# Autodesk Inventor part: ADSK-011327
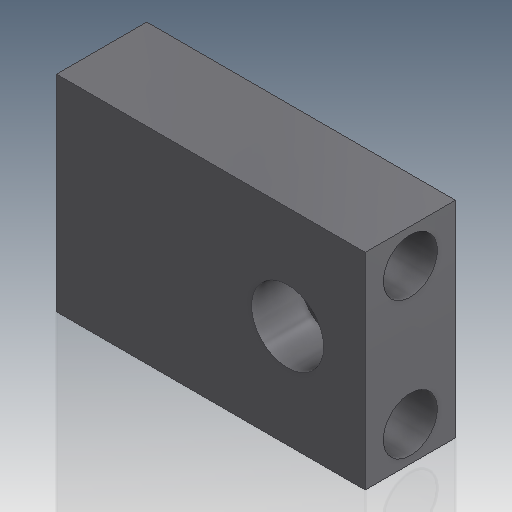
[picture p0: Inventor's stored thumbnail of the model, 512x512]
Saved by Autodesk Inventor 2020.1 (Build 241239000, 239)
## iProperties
Created: 1999-12
Part Number: ADSK-011327
Material: Acier doux
Description: PLT-03,FH,CP,10,022,032,556,BLOCK,MOUNTING
Document SubType Name: Modeling
Designer: sspink
Density: 7.86 g/cm^3
Appearance: Metal-Steel(Polish)
Mass: 782.796 g
Surface Area: 232.844 cm^2
Volume: 99.5924 cm^3
Control State: 0
Checked Out: False
Last Check In By: sspink
Last Check In Date: 1999-12-22
Master: False
Shininess: 0.0
Length Units: 11269
Angle Units: 11279
Time Units: 11290
Mass Units: 11283
Length Display Precision: 3
Angle Display Precision: 2
Compacted: True
Dimensions: 85,5x57x25 mm
Mass: 0,783 kg
DocNumber: ADSK-011327.ipt
Folder: 01 - Themengebiete\Simplification\01 - Packaging machine\
VDS_Category: 3D Komponenten
Density: 0.0
Volumn: 0.0
Area: 0.0
PropertySet Name: Model Information
Author: sspink
Revision Number: -
Title: fixing plate
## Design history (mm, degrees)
sketch "Skizze4"
  geometry: C1 r 6.75 at (-21.25, 0) reference; 2 further points
  constraints: 1 coincident
hole "Bohrung3" sketch "Skizze4" at (-21.25, 0) diameter "d22" = 25; stored, may be unused: countersink angle "d26" = 82 deg, drill point angle "d28" = 0 deg; dims "d23" = 6, "d24" = 20, "d25" = 13.5, "d27" = 6
sketch "Sketch3"
  geometry: L1 (0, 57)-(-25, 57) reference; L2 (-12.5, 47.5)-(-12.5, 9.5); L3 (-25, 57)-(-25, 0) reference; 3 further points
  constraints: 3 midpoint, 2 end point, 1 horizontal alignment, 1 vertical, 1 vertical alignment
  dimensions: "d20" = 38 distance of L2.end L2.start
node "Hole2" dims "d13" = 9, "d14" = 15, "d15" = 15, "d16" = 60 deg, "d17" = 19.05, "d18" = 118 deg, "d19" = 6
node "Solide1"
  node "Extrusion1" dims "d2" = 25, "d3" = 0
  node "Hole1" dims "d5" = 13.5, "d6" = 20, "d7" = 13.5, "d8" = 60 deg, "d9" = 19.05, "d10" = 118 deg, "d21" = 6
sketch "Sketch1"
  geometry: L1 (-42.75, 28.5)-(42.75, 28.5); L2 (42.75, 28.5)-(42.75, -28.5); L3 (42.75, -28.5)-(-42.75, -28.5); L4 (-42.75, -28.5)-(-42.75, 28.5); 3 further points
  constraints: 8 end point, 2 midpoint, 2 parallel, 1 horizontal, 1 horizontal alignment, 1 perpendicular, 1 vertical alignment
  dimensions: "d0" = 85.5 distance of L1.start L1.end; "d1" = 57 distance of L1.end L2.end
sketch "Sketch2"
  geometry: L1 (-42.75, -28.5)-(-42.75, 28.5) reference; L2 (42.75, 28.5)-(42.75, -28.5) reference; L3 (-42.75, 0)-(42.75, 0); 1 further point
  constraints: 2 end point, 2 midpoint, 1 point on line
  dimensions: "d4" = 21.5 distance from line of point (21.25, 0) L2
node "Corps solides"
node "Corps surfaciques"
